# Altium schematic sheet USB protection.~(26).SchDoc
size A3; SheetNumber: 7; SheetTotal: 7
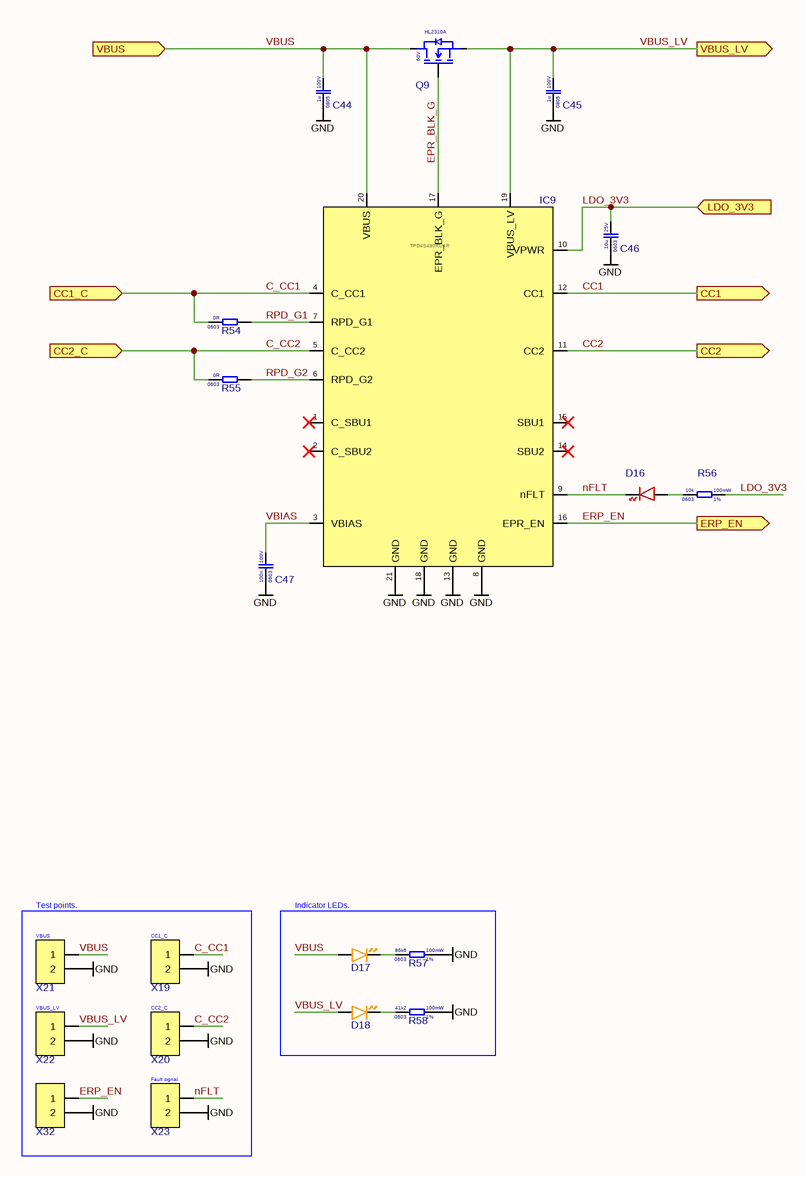
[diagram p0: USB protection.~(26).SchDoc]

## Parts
C44  Voltage Rating: 100V  Case Code (Imperial): 0805  Capacitance: 1u  [Cap_0805]  (hidden comment: CC0805KKX7R0BB105)
C45  Voltage Rating: 100V  Case Code (Imperial): 0805  Capacitance: 1u  [Cap_0805]  (hidden comment: CC0805KKX7R0BB105)
C46  Voltage Rating: 25V  Case Code (Imperial): 0603  Capacitance: 10u  [CAP 0603]  (hidden comment: CL10A106MA8NRNC)
C47  Voltage Rating: 100V  Case Code (Imperial): 0603  Capacitance: 100n  [CAP 0603]  (hidden comment: CC0603KRX7R0BB104)
D16  XL-1608SURC-06  [DIODE_0603]  (value not drawn)
D17  XL-1608UOC-06  [DIODE_0603]  (value not drawn)
D18  XL-1608UOC-06  [DIODE_0603]  (value not drawn)
IC9  TPD4S480RUKR  [WQFN (20)]
Q9  Voltage: 60V  [SOT-23 GSD]  (hidden comment: HL2310A)
R54  Resistance: 0R  Case Code (Imperial): 0603  [RES_0603]  (hidden comment: 0603WAF0000T5E)
R55  Resistance: 0R  Case Code (Imperial): 0603  [RES_0603]  (hidden comment: 0603WAF0000T5E)
R56  Resistance Tolerance: 1%  Resistance: 10k  Power Rating: 100mW  Case Code (Imperial): 0603  [RES_0603]  (hidden comment: 0603WAF1002T5E)
R57  Resistance Tolerance: 1%  Resistance: 86k6  Power Rating: 100mW  Case Code (Imperial): 0603  [RES_0603]  (hidden comment: 0603WAF8662T5E)
R58  Resistance Tolerance: 1%  Resistance: 41k2  Power Rating: 100mW  Case Code (Imperial): 0603  [RES_0603]  (hidden comment: 0603WAF4122T5E)
X19  ZX-PZ1.27-1-2PZZ  [Pin header 1x2 1.27mmP THT Vertical]  (value not drawn)
X20  ZX-PZ1.27-1-2PZZ  [Pin header 1x2 1.27mmP THT Vertical]  (value not drawn)
X21  ZX-PZ1.27-1-2PZZ  [Pin header 1x2 1.27mmP THT Vertical]  (value not drawn)
X22  ZX-PZ1.27-1-2PZZ  [Pin header 1x2 1.27mmP THT Vertical]  (value not drawn)
X23  ZX-PZ1.27-1-2PZZ  [Pin header 1x2 1.27mmP THT Vertical]  (value not drawn)
X32  ZX-PZ1.27-1-2PZZ  [Pin header 1x2 1.27mmP THT Vertical]  (value not drawn)

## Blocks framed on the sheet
Test points.: X19-X23 X32
Indicator LEDs.: D17 D18 R57 R58

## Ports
CC1 (out, see Arhitecture[3B], USB PD[2C]), CC1_C (in, see Arhitecture[2B]), CC2 (out, see Arhitecture[3B], USB PD[2C]), CC2_C (in, see Arhitecture[2B]), ERP_EN (out, see Arhitecture[3B], USB PD[5B]), LDO_3V3 (in, see Arhitecture[3B], USB PD[3C]), VBUS (in, see Arhitecture[2B], Power path switch[3B]), VBUS_LV (out, see Arhitecture[3B], USB PD[3B])

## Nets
GND: C44.1 C45.1 C46.1 C47.1 IC9.8(GND) IC9.13(GND) IC9.18(GND) IC9.21(GND) R57.2 R58.2 X19.2 X20.2 X21.2 X22.2 X23.2 X32.2
C_CC1: IC9.4(C_CC1) R54.1 X19.1 ; port CC1_C
C_CC2: IC9.5(C_CC2) R55.1 X20.1 ; port CC2_C
CC1: IC9.12(CC1) ; port CC1
CC2: IC9.11(CC2) ; port CC2
EPR_BLK_G: IC9.17(EPR_BLK_G) Q9.G
ERP_EN: IC9.16(EPR_EN) X32.1 ; port ERP_EN
LDO_3V3: C46.2 IC9.10(VPWR) R56.2 ; port LDO_3V3
nFLT: D16.K IC9.9(nFLT) X23.1
RPD_G1: IC9.7(RPD_G1) R54.2
RPD_G2: IC9.6(RPD_G2) R55.2
VBIAS: C47.2 IC9.3(VBIAS)
VBUS: C44.2 D17.A IC9.20(VBUS) Q9.D X21.1 ; port VBUS
VBUS_LV: C45.2 D18.A IC9.19(VBUS_LV) Q9.S X22.1 ; port VBUS_LV
NetD16_A: D16.A R56.1
NetD17_K: D17.K R57.1
NetD18_K: D18.K R58.1

Not connected (* = marked no-connect by the designer): IC9 1(C_SBU1)* 2(C_SBU2)* 14(SBU2)* 15(SBU1)*

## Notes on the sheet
- (near X21) VBUS
- (near X19) CC1_C
- (near X22) VBUS_LV
- (near X20) CC2_C
- (near X23) Fault signal.

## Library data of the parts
C44 C45 = CC0805KKX7R0BB105: Cap 1uF 100V 0805 X7R; Manufacturer: Yageo
C46 = CL10A106MA8NRNC: Cap 10uF 25V 0603 X5R; Manufacturer: Samsung
C47 = CC0603KRX7R0BB104: Cap 100nF 100V 0603 X7R; Manufacturer: YAGEO
D16 = XL-1608SURC-06: LED Red 0603 25mA; Manufacturer: Xinglight
D17 D18 = XL-1608UOC-06: LED Orange 0603 20mA; Manufacturer: XINGLIGHT
IC9 = TPD4S480RUKR: USB PD protection IC; Manufacturer: Texas Instruments
Q9 = HL2310A: nMOS 60V 3A SOT-23; Manufacturer: hongjiacheng
R54 R55 = 0603WAF0000T5E: Res 0R 0603 1% 100mW 75V; Manufacturer: UNI-ROYAL
R56 = 0603WAF1002T5E: Res 10k 0603 1% 100mW 75V; Manufacturer: Uni-Royal
R57 = 0603WAF8662T5E: Res 86k6 0603 1% 100mW 75V; Manufacturer: Uni-Royal
R58 = 0603WAF4122T5E: Res 41k2 0603 1% 100mW 75V; Manufacturer: Uni-Royal
X19-X23 X32 = ZX-PZ1.27-1-2PZZ: Pin header 1x2 1.27mmP THT Vertical; Manufacturer: Megastar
